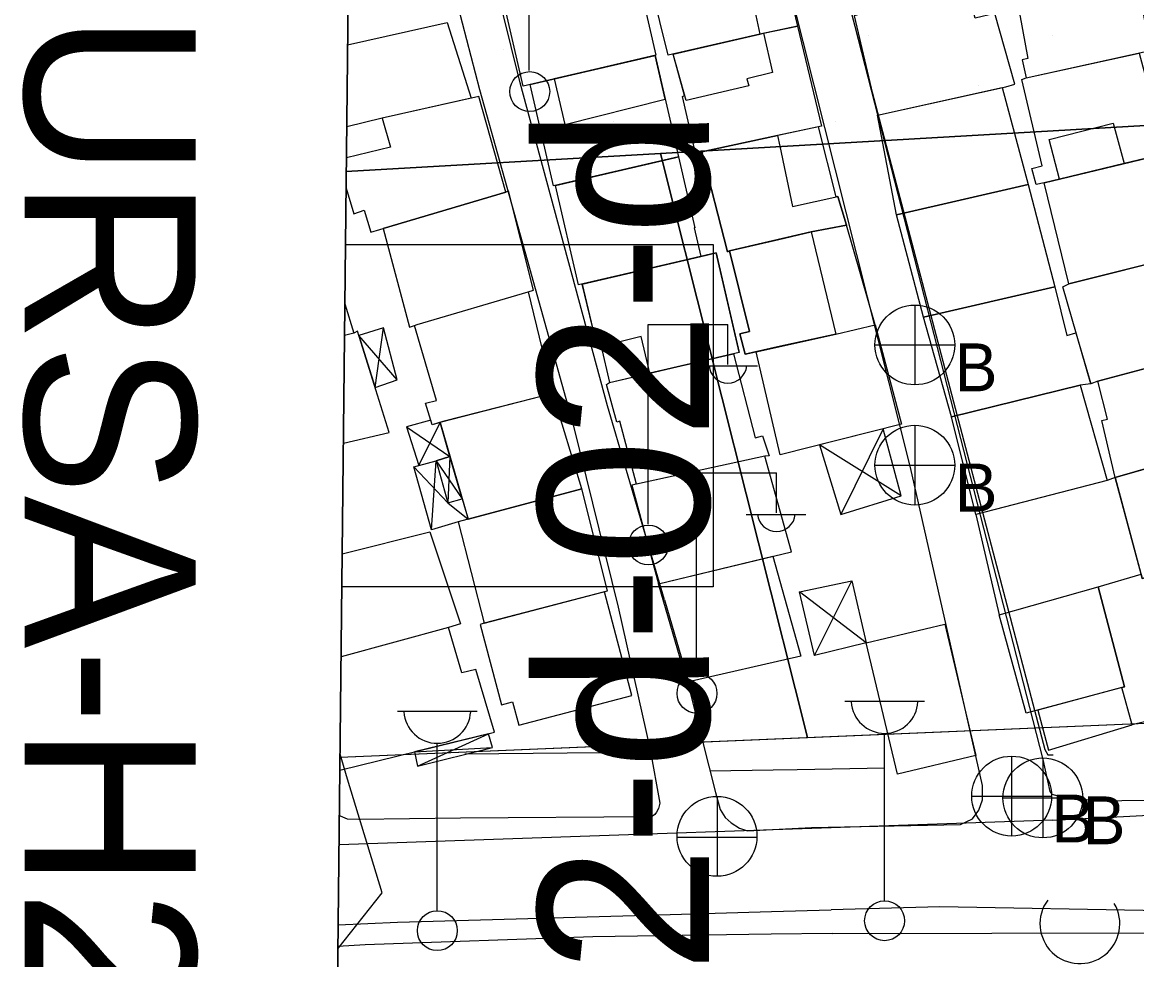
# Model space of a CAD drawing. Extents: x 417997 to 421451, y 4451742 to 4455216.
# Drawn here: x 419095.9 to 419193.6, y 4453629.4 to 4453711.6 of the extents above; entities that cross this region are included whole.
import ezdxf

# ---------------------------------------------------------------- set-up
doc = ezdxf.new("R2010")
doc.units = 0
for name, color, linetype in [('ADAKENARI', 7, 'Continuous'), ('B_Mesken', 7, 'Continuous'), ('B_Sundurma', 7, 'Continuous'), ('B_Teras', 7, 'Continuous'), ('Default', 7, 'Continuous'), ('KALDIRIM', 7, 'Continuous'), ('LJ_SEMBOL', 7, 'Continuous'), ('PAFTALAMA', 7, 'Continuous'), ('PL_AYA_PARK_DINLENME', 7, 'Continuous'), ('PL_K_BHA', 7, 'Continuous'), ('PL_TİCK', 7, 'Continuous'), ('riskli alan', 7, 'Continuous'), ('S_Cad_Sok_Lambasi', 7, 'Continuous'), ('S_Elektrik_Diregi', 7, 'Continuous'), ('S_Minare', 7, 'Continuous'), ('S_Rogar_Kapagi', 7, 'Continuous'), ('S_Rogar_Kapagi_Buski', 7, 'Continuous'), ('SN_3_DERECE_KAYNAK_KORUMA', 7, 'Continuous'), ('TR_PARKALANI', 7, 'Continuous'), ('TR_TİCK', 7, 'Continuous'), ('TR_YONETIMMERK', 7, 'Continuous'), ('Y_Lejant', 7, 'Continuous'), ('Yol_Kaldirim_kenari_bordurtasi', 7, 'Continuous'), ('Yol_Sose', 7, 'Continuous')]:
    doc.layers.add(name, color=color, linetype=linetype)

# ---------------------------------------------------------------- blocks, each defined once
blk = doc.blocks.new('POINT_DISPLAY')
at = {"layer": 'Default'}
blk.add_line((0, 0), (0, 0), dxfattribs=at)

msp = doc.modelspace()

# ---------------------------------------------------------------- linework, layer by layer
at = {"layer": 'ADAKENARI'}
for p, q in [((419124.273, 4453698.526), (419324.954, 4453710.095)), ((419124.273, 4453698.526), (419324.954, 4453710.095)), ((419164.709, 4453648.91), (419151.813, 4453700.114)), ((419164.709, 4453648.91), (419151.813, 4453700.114)), ((419123.723, 4453647.173), (419322.839, 4453655.614)), ((419123.723, 4453647.173), (419322.839, 4453655.614))]:
    msp.add_line(p, q, dxfattribs=at)
at = {"layer": 'B_Mesken'}
for points in [[(419161.806, 4453719.825), (419163.83, 4453711.276), (419160.539, 4453710.58), (419152.5, 4453708.711), (419150.349, 4453717.485), (419158.7, 4453719.191)], [(419182.634, 4453716.078), (419184.038, 4453708.442), (419183.548, 4453708.31), (419183.888, 4453706.733), (419194.763, 4453709.125), (419193.102, 4453718.446)], [(419137.77, 4453714.777), (419148.527, 4453717.266), (419149.367, 4453713.635), (419150.246, 4453713.838), (419151.431, 4453708.714), (419139.795, 4453706.022)], [(419169.097, 4453712.255), (419168.799, 4453712.176), (419170.839, 4453703.475), (419182.097, 4453705.963), (419182.901, 4453706.189), (419181.138, 4453712.371), (419179.403, 4453711.977), (419178.756, 4453714.57), (419176.759, 4453714.069), (419170.685, 4453712.645)], [(419163.83, 4453711.276), (419165.946, 4453702.508), (419154.899, 4453700.132), (419153.75, 4453705.114), (419153.943, 4453705.182), (419152.946, 4453708.814), (419160.539, 4453710.58), (419160.857, 4453710.647)], [(419140.392, 4453706.16), (419151.352, 4453708.696), (419153.409, 4453699.805), (419142.449, 4453697.269)], [(419193.807, 4453708.915), (419196.149, 4453700.118), (419192.467, 4453699.23), (419186.806, 4453697.865), (419185.456, 4453697.539), (419184.749, 4453697.381), (419184.38, 4453698.795), (419185.278, 4453699.033), (419183.503, 4453706.603), (419183.888, 4453706.733)], [(419181.785, 4453705.894), (419184.074, 4453697.401), (419172.52, 4453694.731), (419170.839, 4453703.475)], [(419167.214, 4453696.303), (419165.675, 4453702.45), (419162.084, 4453701.678), (419155.439, 4453700.248), (419157.689, 4453691.476), (419157.878, 4453691.581), (419165.023, 4453693.234), (419168.127, 4453693.809), (419167.36, 4453696.335)], [(419187.627, 4453688.689), (419185.456, 4453697.539), (419196.149, 4453700.118), (419198.258, 4453691.342)], [(419142.634, 4453697.312), (419153.049, 4453699.721), (419153.409, 4453699.805), (419154.846, 4453693.593), (419154.775, 4453693.577), (419155.353, 4453691.075), (419144.65, 4453688.599)], [(419174.88, 4453685.762), (419172.52, 4453694.731), (419184.074, 4453697.401), (419186.396, 4453688.412)], [(419127.501, 4453693.531), (419129.825, 4453684.883), (419130.265, 4453685.019), (419130.494, 4453685.123), (419140.21, 4453687.982), (419140.696, 4453688.112), (419138.494, 4453696.841), (419138.258, 4453696.704)], [(419168.127, 4453693.809), (419165.023, 4453693.234), (419157.878, 4453691.581), (419159.615, 4453684.503), (419158.79, 4453684.3), (419159.253, 4453682.519), (419167.195, 4453684.27), (419170.656, 4453685.083)], [(419156.708, 4453691.388), (419144.963, 4453688.651), (419146.26, 4453683.089), (419146.623, 4453683.173), (419147.355, 4453680.031), (419150.884, 4453680.853), (419158.723, 4453682.68)], [(419190.17, 4453680.146), (419189.544, 4453679.907), (419187.09, 4453688.417), (419187.627, 4453688.689), (419197.53, 4453691.16), (419199.81, 4453682.704)], [(419186.396, 4453688.412), (419187.446, 4453684.146), (419188.254, 4453684.379), (419189.544, 4453679.907), (419188.621, 4453679.805), (419177.343, 4453677.014), (419174.88, 4453685.762)], [(419142.376, 4453679.065), (419132.754, 4453676.606), (419131.807, 4453676.311), (419131.216, 4453678.205), (419132.197, 4453678.464), (419130.265, 4453685.019), (419130.494, 4453685.123), (419140.21, 4453687.982)], [(419170.656, 4453685.083), (419172.953, 4453676.371), (419162.313, 4453673.697), (419160.219, 4453682.732), (419167.195, 4453684.27)], [(419149.73, 4453671.122), (419148.263, 4453676.651), (419147.983, 4453676.553), (419147.089, 4453679.869), (419147.355, 4453680.031), (419151.081, 4453680.899), (419158.236, 4453682.554), (419160.124, 4453675.177), (419160.776, 4453675.359), (419161.351, 4453673.609), (419160.987, 4453673.567)], [(419191.689, 4453671.712), (419190.521, 4453676.686), (419191.022, 4453676.817), (419190.17, 4453680.146), (419199.81, 4453682.704), (419201.622, 4453674.559)], [(419188.621, 4453679.805), (419190.994, 4453671.434), (419179.471, 4453668.455), (419177.343, 4453677.014)], [(419132.499, 4453676.527), (419134.95, 4453668.038), (419144.938, 4453670.717), (419142.376, 4453679.065)], [(419201.622, 4453674.559), (419203.706, 4453668.694), (419204.521, 4453665.515), (419197.961, 4453663.846), (419194.058, 4453662.853), (419193.959, 4453663.223), (419191.689, 4453671.712), (419197.308, 4453673.323)], [(419149.317, 4453671.032), (419151.661, 4453662.375), (419163.303, 4453665.182), (419160.987, 4453673.567)], [(419179.471, 4453668.455), (419181.528, 4453659.652), (419190.199, 4453662.11), (419193.959, 4453663.223), (419191.689, 4453671.712), (419190.994, 4453671.434)], [(419136.375, 4453658.92), (419147.191, 4453661.765), (419144.938, 4453670.717), (419134.084, 4453667.806)], [(419154.15, 4453653.773), (419151.661, 4453662.375), (419161.686, 4453664.792), (419164.121, 4453656.041)], [(419190.199, 4453662.11), (419193.959, 4453663.223), (419194.058, 4453662.853), (419197.961, 4453663.846), (419201.228, 4453651.97), (419193.177, 4453650.029), (419192.288, 4453653.298), (419192.515, 4453653.359)], [(419181.528, 4453659.652), (419190.199, 4453662.11), (419192.515, 4453653.359), (419183.899, 4453651.037)], [(419146.908, 4453661.69), (419136.375, 4453658.92), (419136.017, 4453658.826), (419137.872, 4453651.771), (419138.86, 4453652.031), (419139.397, 4453649.987), (419149.301, 4453652.591)], [(419172.594, 4453645.701), (419169.863, 4453657.211), (419176.741, 4453658.843), (419179.472, 4453647.333)], [(419184.915, 4453651.311), (419185.836, 4453647.805), (419193.177, 4453650.029), (419192.288, 4453653.298)]]:
    msp.add_lwpolyline(points, close=True, dxfattribs=at)
for points in [[(419124.393, 4453709.633), (419133.132, 4453711.583), (419135.211, 4453704.954), (419127.414, 4453703.192), (419124.316, 4453702.43)], [(419124.259, 4453697.08), (419124.928, 4453694.825), (419125.846, 4453695.139), (419126.433, 4453693.216), (419138.258, 4453696.704), (419135.89, 4453705.107), (419127.414, 4453703.192), (419128.141, 4453700.65), (419124.287, 4453699.731)], [(419124.15, 4453686.922), (419124.95, 4453684.368), (419124.121, 4453684.148)], [(419124.019, 4453674.698), (419128.033, 4453675.659), (419125.27, 4453684.525), (419124.95, 4453684.368), (419124.121, 4453684.148)], [(419123.916, 4453665.02), (419131.596, 4453666.938), (419134.299, 4453658.867), (419133.234, 4453658.543), (419123.819, 4453655.985)], [(419123.713, 4453646.045), (419137.279, 4453649.368), (419135.621, 4453654.884), (419134.418, 4453654.564), (419133.234, 4453658.543), (419123.819, 4453655.985)]]:
    msp.add_lwpolyline(points, dxfattribs=at)
at = {"layer": 'B_Sundurma'}
for p, q in [((419126.805, 4453679.599), (419127.535, 4453684.827)), ((419128.742, 4453680.251), (419125.387, 4453684.15)), ((419130.63, 4453672.756), (419132.499, 4453676.527)), ((419129.563, 4453676.158), (419133.358, 4453673.553)), ((419171.358, 4453675.97), (419167.639, 4453668.463)), ((419172.936, 4453670.085), (419165.753, 4453674.561)), ((419133.358, 4453673.553), (419133.173, 4453669.473)), ((419130.211, 4453672.648), (419133.173, 4453669.473)), ((419131.753, 4453667.116), (419132.167, 4453673.153)), ((419132.167, 4453673.153), (419134.431, 4453669.835)), ((419133.173, 4453669.473), (419134.95, 4453668.038)), ((419165.331, 4453656.101), (419168.599, 4453662.644)), ((419169.863, 4453657.211), (419164.013, 4453661.67)), ((419130.517, 4453646.405), (419136.744, 4453649.237)), ((419130.244, 4453647.645), (419137.097, 4453648.043))]:
    msp.add_line(p, q, dxfattribs=at)
for points in [[(419126.805, 4453679.599), (419128.742, 4453680.251), (419127.535, 4453684.827), (419125.387, 4453684.15)], [(419129.563, 4453676.158), (419130.63, 4453672.756), (419132.167, 4453673.153), (419133.358, 4453673.553), (419132.499, 4453676.527), (419131.807, 4453676.311), (419131.678, 4453676.724)], [(419172.936, 4453670.085), (419171.358, 4453675.97), (419165.753, 4453674.561), (419167.639, 4453668.463)], [(419133.358, 4453673.553), (419132.167, 4453673.153), (419133.173, 4453669.473), (419134.431, 4453669.835)], [(419134.084, 4453667.806), (419131.753, 4453667.116), (419130.211, 4453672.648), (419132.167, 4453673.153), (419133.173, 4453669.473), (419134.431, 4453669.835), (419134.95, 4453668.038)], [(419169.863, 4453657.211), (419165.331, 4453656.101), (419164.013, 4453661.67), (419168.599, 4453662.644)], [(419130.244, 4453647.645), (419130.517, 4453646.405), (419137.097, 4453648.043), (419136.744, 4453649.237)]]:
    msp.add_lwpolyline(points, close=True, dxfattribs=at)
at = {"layer": 'B_Teras'}
for points in [[(419158.7, 4453719.191), (419160.539, 4453710.58), (419152.5, 4453708.711), (419150.349, 4453717.485)], [(419160.857, 4453710.647), (419161.642, 4453707.203), (419159.39, 4453706.642), (419159.566, 4453706.042), (419154.063, 4453704.745), (419152.946, 4453708.814)], [(419142.517, 4453706.652), (419143.449, 4453702.649), (419152.24, 4453704.856), (419151.352, 4453708.696)], [(419192.467, 4453699.23), (419186.806, 4453697.865), (419185.917, 4453701.344), (419191.501, 4453702.776)], [(419162.28, 4453700.752), (419163.395, 4453695.459), (419167.36, 4453696.335), (419168.127, 4453693.809), (419165.023, 4453693.234), (419162.192, 4453692.579), (419157.878, 4453691.581), (419157.689, 4453691.476), (419155.439, 4453700.248), (419162.084, 4453701.678)], [(419162.091, 4453683.145), (419159.253, 4453682.519), (419158.79, 4453684.3), (419159.615, 4453684.503), (419157.878, 4453691.581), (419162.192, 4453692.579), (419165.023, 4453693.234), (419167.195, 4453684.27)], [(419144.963, 4453688.651), (419155.353, 4453691.075), (419156.708, 4453691.388), (419158.726, 4453682.667), (419150.884, 4453680.853), (419150.142, 4453684.06), (419146.306, 4453683.099)], [(419191.689, 4453671.712), (419194.058, 4453662.853), (419204.521, 4453665.515), (419203.706, 4453668.694), (419199.084, 4453667.291), (419197.308, 4453673.323)]]:
    msp.add_lwpolyline(points, close=True, dxfattribs=at)
at = {"layer": 'KALDIRIM'}
for q in [(419323.38, 4453648.975), (419323.38, 4453648.975), (419123.641, 4453639.488), (419123.641, 4453639.488)]:
    msp.add_line((419186.217, 4453641.661), q, dxfattribs=at)
at = {"layer": 'LJ_SEMBOL'}
for points in [[(419124.205, 4453692.13), (419156.43, 4453692.13), (419156.43, 4453662.13), (419123.883, 4453662.13)], [(419124.205, 4453692.13), (419156.43, 4453692.13), (419156.43, 4453662.13), (419123.883, 4453662.13)], [(419124.205, 4453692.13), (419156.43, 4453692.13)], [(419124.205, 4453692.13), (419156.43, 4453692.13)]]:
    msp.add_lwpolyline(points, dxfattribs=at)
at = {"layer": 'PAFTALAMA'}
msp.add_line((419138.441, 4455021.891), (419108.72, 4452245.779), dxfattribs=at)
msp.add_line((419138.441, 4455021.891), (419108.72, 4452245.779), dxfattribs=at)
at = {"layer": 'PL_AYA_PARK_DINLENME'}
msp.add_line((419124.499, 4453719.599), (419124.273, 4453698.526), dxfattribs=at)
msp.add_line((419124.499, 4453719.599), (419124.273, 4453698.526), dxfattribs=at)
msp.add_lwpolyline([(419124.273, 4453698.526), (419151.813, 4453700.114), (419324.954, 4453710.095), (419321.86, 4453731.334), (419124.499, 4453719.599)], dxfattribs=at)
msp.add_lwpolyline([(419124.273, 4453698.526), (419151.813, 4453700.114), (419324.954, 4453710.095), (419321.86, 4453731.334), (419124.499, 4453719.599)], dxfattribs=at)
at = {"layer": 'PL_K_BHA'}
msp.add_line((419124.273, 4453698.526), (419123.723, 4453647.173), dxfattribs=at)
msp.add_line((419124.273, 4453698.526), (419123.723, 4453647.173), dxfattribs=at)
msp.add_lwpolyline([(419123.723, 4453647.173), (419164.709, 4453648.91), (419151.813, 4453700.114), (419124.273, 4453698.526)], dxfattribs=at)
msp.add_lwpolyline([(419123.723, 4453647.173), (419164.709, 4453648.91), (419151.813, 4453700.114), (419124.273, 4453698.526)], dxfattribs=at)
at = {"layer": 'PL_TİCK'}
msp.add_lwpolyline([(419164.709, 4453648.91), (419322.839, 4453655.614), (419331.388, 4453665.934), (419326.377, 4453700.333), (419324.954, 4453710.095), (419151.813, 4453700.114), (419164.709, 4453648.91)], dxfattribs=at)
msp.add_lwpolyline([(419164.709, 4453648.91), (419322.839, 4453655.614), (419331.388, 4453665.934), (419326.377, 4453700.333), (419324.954, 4453710.095), (419151.813, 4453700.114), (419164.709, 4453648.91)], dxfattribs=at)
at = {"layer": 'riskli alan'}
for p, q in [((419124.39, 4453645.25), (419123.726, 4453647.434)), ((419124.39, 4453645.25), (419123.726, 4453647.434)), ((419127.42, 4453635.28), (419124.39, 4453645.25)), ((419127.42, 4453635.28), (419124.39, 4453645.25)), ((419123.544, 4453630.391), (419127.42, 4453635.28)), ((419123.544, 4453630.391), (419127.42, 4453635.28))]:
    msp.add_line(p, q, dxfattribs=at)
at = {"layer": 'S_Cad_Sok_Lambasi'}
for p, q in [((419167.975, 4453652.096), (419174.975, 4453652.096)), ((419128.757, 4453651.227), (419135.757, 4453651.227)), ((419171.475, 4453634.596), (419171.475, 4453649.272)), ((419132.257, 4453633.727), (419132.257, 4453648.402))]:
    msp.add_line(p, q, dxfattribs=at)
for centre in [(419171.475, 4453632.846), (419132.257, 4453631.977)]:
    msp.add_circle(centre, 1.75, dxfattribs=at)
for centre in [(419171.475, 4453652.201), (419132.257, 4453651.331)]:
    msp.add_arc(centre, 2.929, 183.298, 356.90719, dxfattribs=at)
at = {"layer": 'S_Elektrik_Diregi'}
for p, q in [((419140.324, 4453707.369), (419140.324, 4453724.869)), ((419150.732, 4453667.62), (419150.732, 4453685.12)), ((419150.732, 4453685.12), (419157.732, 4453685.12)), ((419157.732, 4453681.62), (419157.732, 4453685.12)), ((419155.072, 4453681.48), (419160.322, 4453681.48)), ((419154.989, 4453654.611), (419154.989, 4453672.111)), ((419154.989, 4453672.111), (419161.989, 4453672.111)), ((419161.989, 4453668.611), (419161.989, 4453672.111)), ((419159.329, 4453668.471), (419164.579, 4453668.471))]:
    msp.add_line(p, q, dxfattribs=at)
for centre in [(419140.36, 4453705.533), (419150.768, 4453665.785), (419155.025, 4453652.775)]:
    msp.add_circle(centre, 1.75, dxfattribs=at)
for centre in [(419157.733, 4453681.633), (419161.99, 4453668.624)]:
    msp.add_arc(centre, 1.658, 184.83843, 355.14641, dxfattribs=at)
at = {"layer": 'S_Minare'}
msp.add_arc((419188.595, 4453632.585), 3.5, 143.60214, 30.48893, dxfattribs=at)
at = {"layer": 'S_Rogar_Kapagi'}
for p, q in [((419156.829, 4453636.72), (419156.829, 4453643.72)), ((419153.259, 4453640.185), (419160.259, 4453640.185))]:
    msp.add_line(p, q, dxfattribs=at)
msp.add_circle((419156.776, 4453640.249), 3.5, dxfattribs=at)
at = {"layer": 'S_Rogar_Kapagi_Buski'}
for p, q in [((419174.125, 4453686.823), (419174.125, 4453679.823)), ((419170.625, 4453683.323), (419177.625, 4453683.323)), ((419174.125, 4453676.283), (419174.125, 4453669.283)), ((419170.625, 4453672.783), (419177.625, 4453672.783)), ((419182.614, 4453647.273), (419182.614, 4453640.273)), ((419185.344, 4453647.113), (419185.344, 4453640.113)), ((419179.114, 4453643.773), (419186.114, 4453643.773)), ((419181.844, 4453643.613), (419188.844, 4453643.613))]:
    msp.add_line(p, q, dxfattribs=at)
for centre in [(419174.125, 4453683.323), (419174.125, 4453672.783), (419182.614, 4453643.773), (419185.344, 4453643.613)]:
    msp.add_circle(centre, 3.5, dxfattribs=at)
at = {"layer": 'SN_3_DERECE_KAYNAK_KORUMA'}
msp.add_line((419126.495, 4453906.073), (419108.72, 4452245.779), dxfattribs=at)
msp.add_line((419126.495, 4453906.073), (419108.72, 4452245.779), dxfattribs=at)
at = {"layer": 'TR_TİCK'}
msp.add_lwpolyline([(419151.813, 4453700.114), (419164.709, 4453648.91), (419322.839, 4453655.614), (419331.388, 4453665.934), (419326.377, 4453700.333), (419324.954, 4453710.095), (419151.813, 4453700.114)], dxfattribs=at)
msp.add_lwpolyline([(419151.813, 4453700.114), (419164.709, 4453648.91), (419322.839, 4453655.614), (419331.388, 4453665.934), (419326.377, 4453700.333), (419324.954, 4453710.095), (419151.813, 4453700.114)], dxfattribs=at)
at = {"layer": 'Y_Lejant'}
msp.add_lwpolyline([(419138.442, 4455021.89), (421266.409, 4454999.402), (421237.471, 4452223.294), (419108.722, 4452245.778)], close=True, dxfattribs=at)
at = {"layer": 'Yol_Kaldirim_kenari_bordurtasi'}
for points in [[(419150.976, 4453647.541), (419149.629, 4453647.605), (419134.684, 4453647.443)], [(419161.696, 4453646.073), (419163.817, 4453646.11), (419171.502, 4453646.252)], [(419156.164, 4453645.976), (419161.694, 4453646.073)], [(419161.694, 4453646.073), (419161.696, 4453646.073)]]:
    msp.add_lwpolyline(points, dxfattribs=at)
at = {"layer": 'Yol_Sose'}
for points in [[(419126.382, 4453743.429), (419129.709, 4453731.418), (419132.918, 4453717.427), (419135.957, 4453705.725), (419140.344, 4453690.052), (419144.157, 4453676.316), (419148.127, 4453660.323)], [(419152.187, 4453660.99), (419147.185, 4453677.973), (419141.58, 4453698.736), (419139.528, 4453706.299), (419135.544, 4453722.384), (419133.59, 4453730.91), (419130.243, 4453743.387)], [(419173.74, 4453672.581), (419162.46, 4453717.376)], [(419168.56, 4453712.386), (419185.533, 4453647.853), (419185.794, 4453647.398), (419186.248, 4453647.393)], [(419168.56, 4453712.386), (419185.34, 4453646.986), (419185.967, 4453644.161), (419186.128, 4453643.943), (419186.993, 4453643.72), (419190.296, 4453643.37), (419208.236, 4453643.617)], [(419165.078, 4453641.008), (419178.14, 4453641.291), (419179.174, 4453641.771), (419179.722, 4453642.526), (419180.055, 4453643.446), (419180.065, 4453644.693), (419173.74, 4453672.581)], [(419152.187, 4453660.99), (419153.66, 4453655.854), (419156.643, 4453644.088), (419157.07, 4453642.597), (419157.496, 4453641.89), (419158.017, 4453641.421), (419158.742, 4453640.962), (419159.441, 4453640.723), (419161.638, 4453640.834)], [(419148.127, 4453660.323), (419150.925, 4453647.826), (419151.754, 4453643.16), (419151.652, 4453642.674), (419151.482, 4453642.359), (419151.329, 4453642.146), (419151.03, 4453641.941), (419134.283, 4453641.838), (419125.355, 4453641.722), (419124.374, 4453641.756), (419123.777, 4453642.002), (419123.671, 4453642.139)], [(419161.638, 4453640.834), (419161.64, 4453640.834)], [(419161.64, 4453640.834), (419165.078, 4453641.008)], [(419123.568, 4453632.484), (419128.766, 4453632.725), (419152.678, 4453633.385), (419161.561, 4453633.644)], [(419161.561, 4453633.644), (419161.563, 4453633.644)], [(419161.563, 4453633.644), (419166.776, 4453633.795)], [(419275.647, 4453631.558), (419250.674, 4453632.382), (419232.441, 4453632.854), (419195.756, 4453633.717), (419176.32, 4453634.061), (419166.776, 4453633.795)], [(419161.54, 4453631.661), (419145.907, 4453631.433), (419125.942, 4453630.745), (419123.547, 4453630.596)], [(419161.542, 4453631.661), (419161.54, 4453631.661)], [(419166.877, 4453631.739), (419161.542, 4453631.661)], [(419166.877, 4453631.739), (419194.861, 4453631.79), (419211.647, 4453631.303), (419235.805, 4453630.948), (419255.566, 4453630.328), (419271.533, 4453629.874), (419275.19, 4453629.764), (419275.684, 4453629.978), (419276.016, 4453630.521), (419276.046, 4453630.902), (419275.965, 4453631.039), (419275.647, 4453631.558)]]:
    msp.add_lwpolyline(points, dxfattribs=at)

# ---------------------------------------------------------------- block references
at = {"layer": 'TR_PARKALANI', "xscale": 0.1, "yscale": 0.10000000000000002}
for p in [(419152.359, 4453710.486), (419152.359, 4453710.486), (419170.08, 4453710.486), (419170.08, 4453710.486), (419186.237, 4453710.486), (419186.237, 4453710.486), (419138.026, 4453709.183), (419138.026, 4453709.183), (419179.722, 4453706.055), (419179.722, 4453706.055), (419147.668, 4453702.928), (419147.668, 4453702.928), (419167.213, 4453702.928), (419167.213, 4453702.928)]:
    msp.add_blockref('POINT_DISPLAY', p, dxfattribs=at)
at = {"layer": 'TR_YONETIMMERK', "xscale": 0.1, "yscale": 0.10000000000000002}
msp.add_blockref('POINT_DISPLAY', (419146.895, 4453694.686), dxfattribs=at)
msp.add_blockref('POINT_DISPLAY', (419146.895, 4453694.686), dxfattribs=at)

# ---------------------------------------------------------------- texts
at = {"layer": 'PAFTALAMA'}
msp.add_text('BURSA-H22-d-02-d', height=15, rotation=90, dxfattribs=at).set_placement((419156.08, 4453526.827))
msp.add_text('BURSA-H22-d-02-d', height=15, rotation=90, dxfattribs=at).set_placement((419156.08, 4453526.827))
at = {"layer": 'S_Rogar_Kapagi_Buski'}
for p in [(419177.625, 4453679.259), (419177.625, 4453668.719), (419186.114, 4453639.708), (419188.844, 4453639.548)]:
    msp.add_text('B', height=4.2, dxfattribs=at).set_placement(p)
at = {"layer": 'Y_Lejant'}
msp.add_text('BURSA-H22-d-01-c', height=15, rotation=270, dxfattribs=at).set_placement((419096.082, 4453725.829))

doc.saveas('drawing.dxf')
